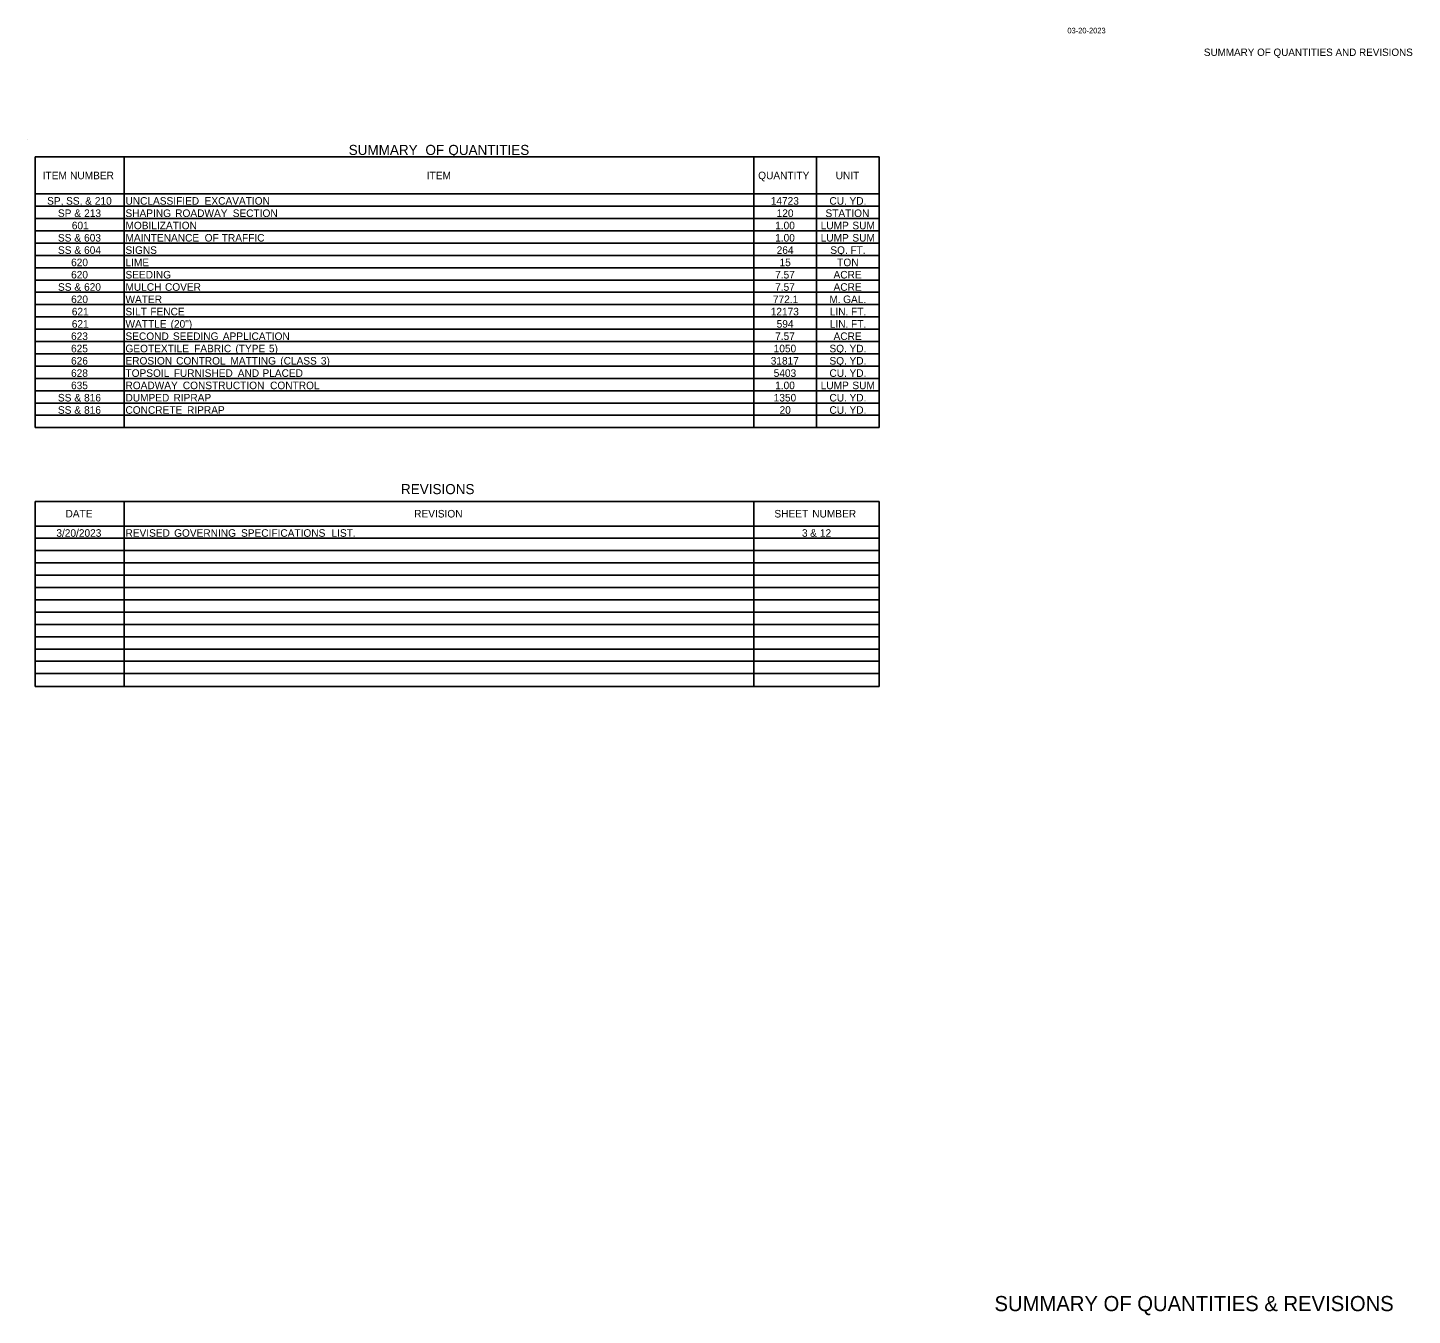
# Model space of a CAD drawing. Extents: x 925 to 1648, y 318 to 522.
# Drawn here: x 1428 to 1647.6, y 318 to 522.2 of the extents above; entities that cross this region are included whole.
import ezdxf

# ---------------------------------------------------------------- set-up
doc = ezdxf.new("R2010")
doc.units = 0
for name, color, linetype in [('Default', 7, 'Continuous'), ('R_Annotation', 7, 'Continuous'), ('R_Border', 7, 'Continuous'), ('R_Border Prem', 7, 'Continuous')]:
    doc.layers.add(name, color=color, linetype=linetype)

msp = doc.modelspace()

# ---------------------------------------------------------------- linework, layer by layer
at = {"layer": 'Default'}
for p, q in [((1429.2, 501.66), (1443.33, 501.66)), ((1429.2, 501.66), (1563.06, 501.66)), ((1429.2, 458.76), (1429.2, 501.66)), ((1429.2, 458.76), (1429.2, 501.66)), ((1443.33, 458.76), (1443.33, 501.66)), ((1543.17, 458.76), (1543.17, 501.66)), ((1553.12, 458.76), (1553.12, 501.66)), ((1563.06, 458.76), (1563.06, 501.66)), ((1429.2, 495.81), (1563.06, 495.81)), ((1429.2, 495.81), (1563.06, 495.81)), ((1443.33, 458.76), (1443.33, 495.81)), ((1543.17, 458.76), (1543.17, 495.81)), ((1553.12, 458.76), (1553.12, 495.81)), ((1563.06, 458.76), (1563.06, 495.81)), ((1429.2, 493.86), (1563.06, 493.86)), ((1429.2, 491.91), (1563.06, 491.91)), ((1429.2, 489.96), (1563.06, 489.96)), ((1429.2, 488.01), (1563.06, 488.01)), ((1429.2, 486.06), (1563.06, 486.06)), ((1429.2, 484.11), (1563.06, 484.11)), ((1429.2, 482.16), (1563.06, 482.16)), ((1429.2, 480.21), (1563.06, 480.21)), ((1429.2, 478.26), (1563.06, 478.26)), ((1429.2, 476.31), (1563.06, 476.31)), ((1429.2, 474.36), (1563.06, 474.36)), ((1429.2, 472.41), (1563.06, 472.41)), ((1429.2, 470.46), (1563.06, 470.46)), ((1429.2, 468.51), (1563.06, 468.51)), ((1429.2, 466.56), (1563.06, 466.56)), ((1429.2, 464.61), (1563.06, 464.61)), ((1429.2, 462.66), (1563.06, 462.66)), ((1429.2, 460.71), (1563.06, 460.71)), ((1429.2, 458.76), (1563.06, 458.76)), ((1429.2, 447.06), (1563.06, 447.06)), ((1429.2, 447.06), (1443.33, 447.06)), ((1429.2, 417.71), (1429.2, 447.06)), ((1429.2, 417.71), (1429.2, 447.06)), ((1443.33, 417.71), (1443.33, 447.06)), ((1543.17, 447.06), (1563.06, 447.06)), ((1543.17, 443.16), (1543.17, 447.06)), ((1543.17, 417.71), (1543.17, 447.06)), ((1563.06, 417.71), (1563.06, 447.06)), ((1563.06, 417.71), (1563.06, 447.06)), ((1429.2, 443.16), (1563.06, 443.16)), ((1429.2, 441.21), (1563.06, 441.21)), ((1429.2, 439.26), (1563.06, 439.26)), ((1429.2, 437.31), (1563.06, 437.31)), ((1429.2, 435.36), (1563.06, 435.36)), ((1429.2, 433.41), (1563.06, 433.41)), ((1429.2, 431.46), (1563.06, 431.46)), ((1429.2, 429.51), (1563.06, 429.51)), ((1429.2, 427.56), (1563.06, 427.56)), ((1429.2, 425.61), (1563.06, 425.61)), ((1429.2, 423.66), (1563.06, 423.66)), ((1429.2, 421.71), (1563.06, 421.71)), ((1429.2, 419.76), (1563.06, 419.76)), ((1429.2, 417.71), (1563.06, 417.71))]:
    msp.add_line(p, q, dxfattribs=at)
at = {"layer": 'R_Border Prem'}
msp.add_line((1428.03, 504.39), (1428.03, 504.39), dxfattribs=at)

# ---------------------------------------------------------------- texts
at = {"layer": 'Default'}
for s, height, p in [(' SUMMARY', 1.6, (1478.33, 501.98)), (' OF', 1.6, (1490.5, 501.98)), (' QUANTITIES', 1.6, (1494.13, 501.98)), ('ITEM', 1.2, (1430.41, 498.13)), (' NUMBER', 1.2, (1434.3, 498.13)), ('ITEM', 1.2, (1491.31, 498.13)), ('QUANTITY', 1.2, (1543.86, 498.13)), ('UNIT', 1.2, (1556.15, 498.13)), ('SP,', 1.2, (1431.11, 494.1)), (' SS,', 1.2, (1433.67, 494.1)), (' &', 1.2, (1436.69, 494.1)), (' 210', 1.2, (1438.23, 494.1)), ('UNCLASSIFIED', 1.2, (1443.53, 494.1)), (' EXCAVATION', 1.2, (1455.64, 494.1)), ('14723', 1.2, (1545.85, 494.1)), ('CU.', 1.2, (1555.16, 494.1)), (' YD.', 1.2, (1557.9, 494.1)), ('SP', 1.2, (1432.82, 492.15)), (' &', 1.2, (1434.98, 492.15)), (' 213', 1.2, (1436.53, 492.15)), ('SHAPING', 1.2, (1443.53, 492.15)), (' ROADWAY', 1.2, (1450.97, 492.15)), (' SECTION', 1.2, (1460.09, 492.15)), ('120', 1.2, (1546.79, 492.15)), ('STATION', 1.2, (1554.53, 492.15)), ('601', 1.2, (1435.02, 490.2)), ('MOBILIZATION', 1.2, (1443.53, 490.2)), ('1.00', 1.2, (1546.55, 490.2)), ('LUMP', 1.2, (1553.77, 490.2)), (' SUM', 1.2, (1558.35, 490.2)), ('SS', 1.2, (1432.82, 488.25)), ('SS', 1.2, (1432.83, 486.3)), (' &', 1.2, (1434.97, 488.25)), (' &', 1.2, (1434.98, 486.3)), (' 603', 1.2, (1436.52, 488.25)), (' 604', 1.2, (1436.52, 486.3)), ('SIGNS', 1.2, (1443.53, 486.3)), ('MAINTENANCE', 1.2, (1443.53, 488.25)), (' OF', 1.2, (1455.64, 488.25)), (' TRAFFIC', 1.2, (1458.36, 488.25)), ('1.00', 1.2, (1546.55, 488.25)), ('264', 1.2, (1546.79, 486.3)), ('LUMP', 1.2, (1553.77, 488.25)), ('SQ.', 1.2, (1555.3, 486.3)), (' FT.', 1.2, (1558.04, 486.3)), (' SUM', 1.2, (1558.35, 488.25)), ('620', 1.2, (1434.91, 484.35)), ('LIME', 1.2, (1443.53, 484.35)), ('15', 1.2, (1547.25, 484.35)), ('TON', 1.2, (1556.39, 484.35)), ('620', 1.2, (1434.91, 482.4)), ('SEEDING', 1.2, (1443.53, 482.4)), ('7.57', 1.2, (1546.55, 482.4)), ('ACRE', 1.2, (1555.81, 482.4)), ('SS', 1.2, (1432.83, 480.45)), (' &', 1.2, (1434.98, 480.45)), (' 620', 1.2, (1436.52, 480.45)), ('MULCH', 1.2, (1443.53, 480.45)), (' COVER', 1.2, (1449.35, 480.45)), ('7.57', 1.2, (1546.55, 480.45)), ('ACRE', 1.2, (1555.81, 480.45)), ('620', 1.2, (1434.91, 478.5)), ('WATER', 1.2, (1443.53, 478.5)), ('772.1', 1.2, (1546.2, 478.5)), ('M.', 1.2, (1555.16, 478.5)), (' GAL.', 1.2, (1556.88, 478.5)), ('621', 1.2, (1435.02, 476.55)), ('SILT', 1.2, (1443.53, 476.55)), (' FENCE', 1.2, (1447.03, 476.55)), ('12173', 1.2, (1545.85, 476.55)), ('LIN.', 1.2, (1555.21, 476.55)), (' FT.', 1.2, (1558.14, 476.55)), ('621', 1.2, (1435.02, 474.6)), ('WATTLE', 1.2, (1443.53, 474.6)), (' (20")', 1.2, (1450.24, 474.6)), ('594', 1.2, (1546.79, 474.6)), ('LIN.', 1.2, (1555.21, 474.6)), (' FT.', 1.2, (1558.14, 474.6)), ('623', 1.2, (1434.9, 472.65)), ('SECOND', 1.2, (1443.53, 472.65)), (' SEEDING', 1.2, (1450.61, 472.65)), (' APPLICATION', 1.2, (1458.52, 472.65)), ('7.57', 1.2, (1546.55, 472.65)), ('ACRE', 1.2, (1555.81, 472.65)), ('625', 1.2, (1434.9, 470.7)), ('626', 1.2, (1434.9, 468.75)), ('GEOTEXTILE', 1.2, (1443.53, 470.7)), ('EROSION', 1.2, (1443.53, 468.75)), (' CONTROL', 1.2, (1451.12, 468.75)), (' FABRIC', 1.2, (1453.97, 470.7)), (' MATTING', 1.2, (1459.73, 468.75)), (' (TYPE', 1.2, (1460.52, 470.7)), (' 5)', 1.2, (1465.83, 470.7)), (' (CLASS', 1.2, (1467.63, 468.75)), (' 3)', 1.2, (1474.07, 468.75)), ('31817', 1.2, (1545.85, 468.75)), ('1050', 1.2, (1546.32, 470.7)), ('SQ.', 1.2, (1555.16, 470.7)), ('SQ.', 1.2, (1555.16, 468.75)), (' YD.', 1.2, (1557.9, 470.7)), (' YD.', 1.2, (1557.9, 468.75)), ('628', 1.2, (1434.9, 466.8)), ('TOPSOIL', 1.2, (1443.53, 466.8)), (' FURNISHED', 1.2, (1450.74, 466.8)), (' AND', 1.2, (1460.89, 466.8)), (' PLACED', 1.2, (1464.81, 466.8)), ('5403', 1.2, (1546.32, 466.8)), ('CU.', 1.2, (1555.16, 466.8)), (' YD.', 1.2, (1557.9, 466.8)), ('635', 1.2, (1434.9, 464.85)), ('ROADWAY', 1.2, (1443.53, 464.85)), (' CONSTRUCTION', 1.2, (1452.18, 464.85)), (' CONTROL', 1.2, (1466.02, 464.85)), ('1.00', 1.2, (1546.55, 464.85)), ('LUMP', 1.2, (1553.77, 464.85)), (' SUM', 1.2, (1558.35, 464.85)), ('SS', 1.2, (1432.82, 462.9)), (' &', 1.2, (1434.97, 462.9)), (' 816', 1.2, (1436.52, 462.9)), ('DUMPED', 1.2, (1443.53, 462.9)), (' RIPRAP', 1.2, (1450.7, 462.9)), ('1350', 1.2, (1546.32, 462.9)), ('CU.', 1.2, (1555.16, 462.9)), (' YD.', 1.2, (1557.9, 462.9)), ('SS', 1.2, (1432.82, 460.95)), (' &', 1.2, (1434.97, 460.95)), (' 816', 1.2, (1436.52, 460.95)), ('CONCRETE', 1.2, (1443.53, 460.95)), (' RIPRAP', 1.2, (1452.85, 460.95)), ('20', 1.2, (1547.25, 460.95)), ('CU.', 1.2, (1555.16, 460.95)), (' YD.', 1.2, (1557.9, 460.95)), ('REVISIONS', 1.6, (1487.22, 448.21)), ('DATE', 1.2, (1434.02, 444.51)), ('REVISION', 1.2, (1489.31, 444.51)), ('SHEET', 1.2, (1546.43, 444.51)), (' NUMBER', 1.2, (1551.99, 444.51)), ('3/20/2023', 1.2, (1432.57, 441.45)), ('REVISED', 1.2, (1443.53, 441.45)), (' GOVERNING', 1.2, (1450.8, 441.45)), (' SPECIFICATIONS', 1.2, (1461.41, 441.45)), (' LIST.', 1.2, (1475.76, 441.45)), ('3', 1.2, (1550.8, 441.45)), (' &', 1.2, (1551.65, 441.45)), (' 12', 1.2, (1553.2, 441.45))]:
    msp.add_text(s, height=height, dxfattribs=at).set_placement(p)
at = {"layer": 'R_Annotation'}
msp.add_text('SUMMARY OF QUANTITIES & REVISIONS', height=2.4, dxfattribs=at).set_placement((1581.33, 318.69))
at = {"layer": 'R_Border'}
msp.add_text('03-20-2023', height=0.887, dxfattribs=at).set_placement((1592.89, 521.26))
msp.add_text('SUMMARY OF QUANTITIES AND REVISIONS', height=1.17, rotation=360, dxfattribs=at).set_placement((1614.54, 517.68))

doc.saveas('drawing.dxf')
